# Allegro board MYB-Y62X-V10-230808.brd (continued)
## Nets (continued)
SOC_MCU_RESETZ: C240.1 D44.1 R414.2 U43.L21
SOC_MCU_SPI0_CLK: R158.2 U18.8(B1) U43.L53
SOC_MCU_SPI0_CS0: R159.2 U18.1(B2) U43.L2
SOC_MCU_SPI0_D0: R148.2 R160.2 U43.L3
SOC_MCU_SPI0_D1: R127.2 U43.L4
SOC_MCU_UART0_RXD: R12.1 U43.L1
SOC_MCU_UART0_TXD: R562.1 U43.L58
SOC_MMC1_CLK: D5.2 J2.5(CLK) R37.2 U43.149
SOC_MMC1_CMD: D4.2 J2.3(CMD) R36.2 U43.156
SOC_MMC1_DAT0: D6.2 J2.7(DAT0) R38.2 U43.155
SOC_MMC1_DAT1: D7.2 J2.8(DAT1) R39.2 U43.154
SOC_MMC1_DAT2: D2.2 J2.1(DAT2) R34.2 U43.158
SOC_MMC1_DAT3: D3.2 J2.2(DAT3) R35.2 U43.157
SOC_MMC1_SDCD: D8.2 J2.9(CD) R40.2 U43.159
SOC_MMC2_CLK: R85.1 U43.144
SOC_MMC2_CMD: R84.1 U43.147
SOC_MMC2_DAT0: R78.1 U43.146
SOC_MMC2_DAT1: R80.1 U43.145
SOC_MMC2_DAT2: R82.1 U43.153
SOC_MMC2_DAT3: R83.1 U43.151
SOC_MMC2_SDCD: R308.2 U29.6(INTB/OUT3) U43.148
SOC_OSPI0_CLK: R51.2 U43.132
SOC_OSPI0_CSN0: R54.2 U43.128
SOC_OSPI0_CSN1: R285.1 U43.129
SOC_OSPI0_DQ0: R52.2 U43.139
SOC_OSPI0_DQ1: R53.2 U43.138
SOC_OSPI0_DQ2: R55.2 U43.137
SOC_OSPI0_DQ3: R56.2 U43.140
SOC_OSPI0_DQ4: R58.2 U43.141
SOC_OSPI0_DQ5: R59.2 U43.133
SOC_OSPI0_DQ6: R60.2 U43.136
SOC_OSPI0_DQ7: R61.2 U43.142
SOC_OSPI0_DQS: R62.2 R63.1 U43.135
SOC_OSPI0_ECC_FAIL: R57.2 U43.131
SOC_OSPI0_LBCLK: R63.2 U43.127
SOC_OSPI0_RESETOUT1: U8.1(B) U43.130
SOC_PORZ_OUT: U35.2(A) U39.2(A) U43.L19
SOC_RESET_REQZ: C242.1 D46.1 R416.2 U43.L17
SOC_RESETSTATZ: U8.2(A) U43.L18
SOC_RGMII1_RD0: R358.2 U43.72
SOC_RGMII1_RD0_R: R358.1 R371.2 R372.1 U33.26(RXD0/RXDLY)
SOC_RGMII1_RD1: R356.2 U43.73
SOC_RGMII1_RD1_R: R356.1 R376.1 U33.25(RXD1/CFG_MODE0)
SOC_RGMII1_RD2: R357.2 U43.67
SOC_RGMII1_RD2_R: R357.1 R377.1 U33.24(RXD2/CFG_MODE1)
SOC_RGMII1_RD3: R359.2 U43.71
SOC_RGMII1_RD3_R: R359.1 R378.1 U33.23(RXD3/CFG_MODE2)
SOC_RGMII1_RX_CTL: R355.2 U43.68
SOC_RGMII1_RXC: R354.2 U43.70
SOC_RGMII1_RXC_R: R354.1 R369.2 R374.1 U33.28(RX_CLK/PHYAD1)
SOC_RGMII1_RXCTL_R: R355.1 R368.2 R375.1 U33.27(RX_DV/PHYAD2)
SOC_RGMII1_TD0: R352.2 U43.65
SOC_RGMII1_TD0_R: R352.1 U33.19(TXD0)
SOC_RGMII1_TD1: R350.2 U43.66
SOC_RGMII1_TD1_R: R350.1 U33.18(TXD1)
SOC_RGMII1_TD2: R351.2 U43.61
SOC_RGMII1_TD2_R: R351.1 U33.17(TXD2)
SOC_RGMII1_TD3: R353.2 U43.62
SOC_RGMII1_TD3_R: R353.1 U33.16(TXD3)
SOC_RGMII1_TX_CTL: R349.2 U43.64
SOC_RGMII1_TXC: R348.2 U43.63
SOC_RGMII1_TXC_R: R348.1 U33.21(TX_CLK)
SOC_RGMII1_TXCTL_R: R349.1 U33.20(TX_CTL)
SOC_RGMII2_RD0: R391.2 U43.82
SOC_RGMII2_RD0_R: R391.1 R406.2 R407.1 U37.26(RXD0/RXDLY)
SOC_RGMII2_RD1: R392.2 U43.86
SOC_RGMII2_RD1_R: R392.1 R411.1 U37.25(RXD1/CFG_MODE0)
SOC_RGMII2_RD2: R393.2 U43.85
SOC_RGMII2_RD2_R: R393.1 R412.1 U37.24(RXD2/CFG_MODE1)
SOC_RGMII2_RD3: R394.2 U43.84
SOC_RGMII2_RD3_R: R394.1 R413.1 U37.23(RXD3/CFG_MODE2)
SOC_RGMII2_RX_CTL: R390.2 U43.83
SOC_RGMII2_RXC: R389.2 U43.81
SOC_RGMII2_RXC_R: R389.1 R404.2 R409.1 U37.28(RX_CLK/PHYAD1)
SOC_RGMII2_RXCTL_R: R390.1 R403.2 R410.1 U37.27(RX_DV/PHYAD2)
SOC_RGMII2_TD0: R383.2 U43.75
SOC_RGMII2_TD0_R: R383.1 U37.19(TXD0)
SOC_RGMII2_TD1: R388.2 U43.76
SOC_RGMII2_TD1_R: R388.1 U37.18(TXD1)
SOC_RGMII2_TD2: R384.2 U43.80
SOC_RGMII2_TD2_R: R384.1 U37.17(TXD2)
SOC_RGMII2_TD3: R385.2 U43.74
SOC_RGMII2_TD3_R: R385.1 U37.16(TXD3)
SOC_RGMII2_TX_CTL: R387.2 U43.77
SOC_RGMII2_TXC: R386.2 U43.79
SOC_RGMII2_TXC_R: R386.1 U37.21(TX_CLK)
SOC_RGMII2_TXCTL_R: R387.1 U37.20(TX_CTL)
SOC_RGMII_MDC: R381.2 R542.1 U37.14(MDC) U43.L23
SOC_RGMII_MDIO: R382.2 R543.1 U37.15(MDIO) U43.L24
SOC_SPI0_CLK: J7.3 U43.L51
SOC_SPI0_CS0: R136.2 R138.1 U43.L50
SOC_SPI0_CS1: R135.2 R137.1 U43.L44
SOC_SPI0_D0: R133.2 R139.1 U43.L52
SOC_SPI0_D1: R134.2 R140.1 U43.L45
SOC_UART0_CTSN: R554.1 U43.124
SOC_UART0_RTSN: R492.1 R493.1 R494.1 U43.123
SOC_UART0_RXD: R560.1 U43.125
SOC_UART0_TXD: R5.1 U43.126
SOC_UART1_CTSN: U43.L12 U47.42(UART_RTS)
SOC_UART1_DCDN: R142.1 U43.L5
SOC_UART1_DSRN: R291.1 R444.1 R489.1 U43.L6
SOC_UART1_DTRN: R260.1 U43.L10
SOC_UART1_RIN: R263.1 U43.L9
SOC_UART1_RTSN: U43.L11 U47.43(UART_CTS)
SOC_UART1_RXD: R81.1 U43.L7
SOC_UART1_TXD: R79.1 U43.L8
SOC_UART4_RXD: R283.1 U43.L25
SOC_UART4_TXD: R280.1 U43.L26
SOC_USB0_DM: L9.1 U43.41
SOC_USB0_DP: L9.4 U43.40
SOC_USB0_DRVVBUS: R317.2 U43.L46
SOC_USB1_DM: U28.30(DMU) U43.44
SOC_USB1_DP: U28.31(DPU) U43.43
SOC_USB1_DRVVBUS: R274.1 U43.L49
SOC_VOUT0_DATA0: R163.1 U43.95
SOC_VOUT0_DATA1: R164.1 U43.107
SOC_VOUT0_DATA2: R165.1 U43.101
SOC_VOUT0_DATA3: R166.1 U43.106
SOC_VOUT0_DATA4: R167.1 U43.99
SOC_VOUT0_DATA5: R168.1 U43.105
SOC_VOUT0_DATA6: R169.1 U43.92
SOC_VOUT0_DATA7: R170.1 U43.98
SOC_VOUT0_DATA8: R171.1 U43.93
SOC_VOUT0_DATA9: R172.1 U43.L29
SOC_VOUT0_DATA10: R173.1 U43.117
SOC_VOUT0_DATA11: R174.1 U43.L27
SOC_VOUT0_DATA12: R175.1 U43.97
SOC_VOUT0_DATA13: R176.1 U43.L30
SOC_VOUT0_DATA14: R177.1 U43.94
SOC_VOUT0_DATA15: R178.1 U43.L28
SOC_VOUT0_DATA16/BOOTMODE08: R179.1 R197.1 U43.115
SOC_VOUT0_DATA17/BOOTMODE09: R180.1 R199.1 U43.113
SOC_VOUT0_DATA18/BOOTMODE10: R181.1 R200.1 U43.112
SOC_VOUT0_DATA19/BOOTMODE11: R182.1 R201.1 U43.116
SOC_VOUT0_DATA20/BOOTMODE12: R183.1 R202.1 U43.96
SOC_VOUT0_DATA21/BOOTMODE13: R184.1 R203.1 U43.103
SOC_VOUT0_DATA22/BOOTMODE14: R185.1 R204.1 U43.108
SOC_VOUT0_DATA23/BOOTMODE15: R186.1 R205.1 U43.102
SOC_VOUT0_DE: R194.1 U43.87
SOC_VOUT0_HSYNC: R196.1 U43.88
SOC_VOUT0_PCLK: R198.1 U43.89
SOC_VOUT0_VSYNC: R195.1 U43.90
SOC_WKUP_UART0_RXD: U43.L20 U46.8(B1)
SOC_WKUP_UART0_TXD: U43.L31 U46.1(B2)
USB0CC1: C158.1 R314.1 U29.1(CC1)
USB0CC2: C160.1 R315.1 U29.2(CC2)
USB_5G_DM: J19.9(IO_9) U28.17(DM3)
USB_5G_DP: J19.7(IO_7) U28.18(DP3)
USB_HUB_RST: R487.1 U42.6(P02)
USB_I2C_SCL: R454.2 R473.2 U29.8(SCL/OUT2)
USB_I2C_SDA: R474.2 R494.2 U29.7(SDA/OUT1)
USB_UART_DM: L6.1 U19.4(UDM)
USB_UART_DP: L6.4 U19.3(UDP)
USBA0_DM: D27.2 J16.A2(USBHMA) U28.20(DM2)
USBA0_DP: D28.2 J16.A3(USBHPA) U28.21(DP2)
USBA1_DM: D30.2 J16.B2(USBHMB) U28.23(DM1)
USBA1_DP: D29.2 J16.B3(USBHPB) U28.24(DP1)
USBC_ID: R309.2 R319.1 U29.9(ID)
USER_LED: D54.2(K) U42.8(P04)
USIM1_CLK: J19.32(IO_32) R327.2
USIM1_DATA: J19.34(IO_34) R325.2
USIM1_DET: J17.4(CD) J19.66(IO_66)
USIM1_RST: J19.30(IO_30) R326.2
USIM2_CLK: J19.44(IO_44) R333.2
USIM2_DATA: J19.42(IO_42) R335.2
USIM2_DET: J18.4(CD) J19.40(IO_40)
USIM2_RST: J19.46(IO_46) R332.2
VIO: C96.1 C98.1 U19.5(VIO) U19.6(V3)
W_DISABLE1_N: J19.8(IO_8) R336.2
WAKE_ON_WAN_N: J19.23(IO_23) TP20.1(PIN1)
WIFI_2V2: C273.1 C274.1 C275.1 L13.1 U47.26(2.2VIN)
WWAN_LED_N: D55.2(K) J19.10(IO_10)
N19629412: C321.1 U27.14(LINEIN_L)
N19629418: C322.1 U27.13(LINEIN_R)
N19629536: J14.3(AUD_GND) R570.1
N19629600: C131.1 U27.10(VAG)
N19629602: C132.1 U27.18(CPFLT)
N19629628: R299.1 U27.31(CTRL_ADR0_CS)
N20386876: J9.9 R152.1
N20386882: J9.6 R150.1
N20386885: J9.7 R151.1
N20386918: J9.2 R148.1
N20390587: Q4.1(G) R127.1 R132.1
N20390701: Q4.3(D) R108.2 R112.2
N20390757: C77.1 C78.1 Q3.2(S) R107.2 R108.1 R117.2
N20390883: C78.2 Q3.1(G) R112.1
N20656670: R288.1 Y2.3(OUT/OUTPUT)
N21392930: L11.1 U33.32(LX)
N21392969: R346.2 R542.2 U33.14(MDC)
N21392972: R347.2 R543.2 U33.15(MDIO)
N21393016: R360.2 U33.34(INT_N/PME_N)
N21393026: R362.1 U33.48(RBIAS)
N21393171: C202.1 C203.1 J22.5(CT1) J22.6(CT2)
N21405925: L12.1 U37.32(LX)
N21406011: R395.2 U37.34(INT_N/PME_N)
N21406021: R397.1 U37.48(RBIAS)
N21406166: C221.1 C222.1 J23.5(CT1) J23.6(CT2)
N21450803: R231.2 SW3.2(ON2)
N21450805: R227.2 SW3.3(ON3)
N21473108: C147.1 U28.11(XOUT) Y3.1
N21476694: C146.1 U28.12(XIN) Y3.3
N21477956: R306.2 R487.2 U28.34(XRSTJ)
N21522281: C182.1 D32.2 J17.2(RST) R326.1
N21522507: C184.1 D34.2 J17.7(I/O) R322.2 R325.1
N21526256: C183.1 D33.2 J17.3(CLK) R327.1 TP16.1(PIN1)
N21526274: C199.1 D38.2 J18.7(I/O) R331.2 R335.1
N21544762: C175.1 C176.1 D31.2 J17.1(VCC) R323.2
N21577420: C171.1 U31.1(BS)
N21577422: C171.2 L10.1 U31.6(LX)
N21577513: R324.2 R329.1 U31.4(EN)
N21577585: C177.2 R328.2 R330.1 U31.3(FB)
N21670486: C239.1 D44.2 D45.2 S1.3 S1.4
N21676766: C241.1 D46.2 D47.2 S2.3 S2.4
N21683802: R266.2 R269.2 U23.3((R)RXD)
N21683845: R267.2 R270.1 U23.12(A)
N21683857: R268.2 U23.6((D)TXD)
N21683901: R272.1 R275.1 U23.13(B)
N21683929: R274.2 R276.1 U23.4(R\E\\) U23.5(DE)
N21684314: R278.2 R283.2 U25.3((R)RXD)
N21684387: R280.2 U25.6((D)TXD)
N21684482: R285.2 R287.1 U25.4(R\E\\) U25.5(DE)
N21714485: R279.2 R281.1 U25.12(A)
N21714524: R284.1 R286.1 U25.13(B)
N21838021: C81.1 C82.1 FB3.1 J7.5 J7.6
N21848668: C138.1 U28.38(VD5_IN)
N21848671: R302.1 U28.40(TEST)
N21849105: R300.2 U28.48(OVCB1)
N21849965: R301.2 U28.39(VD33_OUT)
N21884472: D1.2 F1.2 L1.1
N21885565: R3.2 U1.7(PG)
N21885584: C11.1 U1.1(BS)
N21885634: R4.2 R6.1 U1.9(EN)
N21885693: TP3.1(TP) U1.8(MODE)
N21885737: C19.1 R7.2
N21885739: C19.2 R8.2 R9.1 U1.11(FB)
N21885780: TP5.1(TP) U1.10(ILMT)
N21885830: C20.1 U1.12(BYP)
N21893632: C9.1 U1.13(VCC)
N21900346: C37.2 R18.2 R20.1 U3.7(FB)
N22230603: C126.1 R289.2 Y2.1(EN/VCONT/NC)
N22232243: C86.1 R149.2 Y1.1(EN/VCONT/NC)
N22247036: R248.2 U19.9(RST)
N22324946: D23.2 J15.A6(DP1) J15.B6(DP2) L9.3
N22324958: D24.2 J15.A7(DN1) J15.B7(DN2) L9.2
N22324997: R310.2 U29.5(ADR/CON_DET)
N22325047: R311.2 U29.11(EXT_SEL(ENB))
N22325067: R312.2 R313.1 U29.3(PORT)
N22325125: D25.2 J15.A5(CC1) R314.2
N22325136: D26.2 J15.B5(CC2) R315.2
N22325338: Q5.3(D) R316.2 R317.1 U30.4(EN)
N22325344: R318.2 U30.3(F\L\A\G\)
N22325474: Q5.1(G) R319.2
N22325526: C166.1 C167.1 F2.1 J16.A1(VCC#A1)
N22325538: C168.1 C169.1 F3.1 J16.B1(VCC#B1) TP14.1(TP)
N22348627: J6.27(BL_CTR) R137.2
N22348634: J6.28(TP_CS) R139.2
N22348696: J6.36(TP_PEN) R144.2
N22355541: J5.27(BL_CTR) R138.2
N22355547: J5.28(TP_CS) R140.2
N22355619: J5.36(TP_PEN) R146.2
N22387016: C21.1 U2.13(VCC)
N22387130: R10.2 U2.7(PG)
N22387188: C25.1 U2.1(BS)
N22387215: R11.2 R15.1 U2.9(EN)
N22387217: TP6.1(TP) U2.8(MODE)
N22387362: TP8.1(TP) U2.10(ILMT)
N22387364: C31.2 R14.2 R16.1 U2.11(FB)
N22387368: C31.1 R13.2
N22387403: C32.1 U2.12(BYP)
N22404559: C197.1 D36.2 J18.2(RST) R332.1
N22407290: C198.1 D37.2 J18.3(CLK) R333.1
N22407725: D55.1(A) R427.2
N22483474: R104.1 U12.4(Y)
N22483498: C72.1 R106.2
N22483568: R105.1 U13.4(Y)
N22513317: R218.2 SW2.2(ON2)
N22513319: R219.2 SW2.3(ON3)
N22513321: R220.2 SW2.4(ON4)
N22513323: R230.2 SW3.1(ON1)
N22515068: R229.2 SW2.1(ON1)
N22517589: J22.11(YELLOW+) R344.2
N22517591: J22.13(GREEN+) R345.2
N22525013: J23.13(GREEN+) R380.2
N22525015: J23.11(YELLOW+) R379.2
N22597309: R192.2 R461.1 R491.1
N22610391: R539.2 U40.10(NINT)
N22680350: J26.1 U46.5(A1)
N22680357: J26.2 U46.4(A2)
N22683837: C263.1 R502.2 U47.2(RF0)
N22683839: C264.1 D56.2 J27.2(IN) R502.1
N22683943: R81.2 U47.40(UART_TX)
N22683961: R79.2 U47.41(UART_RX)
N22683997: C265.1 R504.2 U47.9(RF1)
N22684003: C266.1 D57.2 J28.2(IN) R504.1
N22684239: R511.2 Y6.1(EN/VCONT/NC)
N22684315: R512.1 Y6.3(OUT/OUTPUT)
N22684386: L13.2 U47.25(LX_OUT)
N22685134: R69.2 R85.2 U47.18(SD_CLK)
N22685150: R70.2 R84.2 U47.17(SD_CMD)
N22685166: R71.2 R83.2 U47.19(SD_D3)
N22685182: R72.2 R82.2 U47.20(SD_D2)
N22685198: R74.2 R80.2 U47.22(SD_D1)
N22685204: R76.2 R78.2 U47.21(SD_D0)
N22709458: R514.2 U48.72(CI2CA)
N22710105: R515.1 U48.36(SPDIF)
N22710530: R516.2 U48.41(SD0)
N22712478: R517.1 U48.69(IO_SEL)
N22712757: R518.1 U48.56(EXT_SWING)
N22714174: R521.2 R545.1 U50.3(EN)
N22724008: Q2.1(B) R524.2
N22724271: R532.2 U53.5(A1)
N22724282: R533.2 U53.4(A2)
N22746676: C294.1 R535.2 Y7.1(EN/VCONT/NC)
N22751077: D58.2 J29.18(+5V)
N22751165: D59.2 R522.1 R523.1
N22767924: R252.2 U20.3(TXD)
N22767926: L7.1 U20.7(CANH)
N22767928: L7.4 R253.1 R255.1
N22767957: L7.3 R254.1 R256.1
N22767970: R257.2 U20.2(RXD)
N22767972: L7.2 U20.6(CANL)
N22768026: C104.1 R255.2 R256.2
N22768266: R260.2 U22.3(TXD)
N22768268: L8.1 U22.7(CANH)
N22768270: L8.4 R261.1 R264.1
N22768305: L8.3 R262.1 R265.1
N22768318: R263.2 U22.2(RXD)
N22768320: L8.2 U22.6(CANL)
N22768352: C112.1 R264.2 R265.2
N22843605: C318.1 U50.4(BP/FB)
N22857632: R161.2 U48.45(SCK)
N22857662: R162.2 U48.44(WS)
N22863110: R142.2 R290.1 R445.1 R452.1
N22863348: R451.1 R453.1 R454.1 R554.2
N22865159: R555.1 U54.15(NOE)
N22941387: Q1.3(D) R5.2 R558.2
N22941439: Q6.2(S) R559.2 R560.2
N22941491: Q7.3(D) R561.2 R562.2
N22941543: Q8.2(S) R12.2 R563.2
N22973519: R419.1 U40.7(FOE)
N22982457: JP1.2(E2) R567.1
N22991878: C321.2 C322.2 R569.1
N23013826: JP2.1(E1) R571.2
N23013829: JP3.1(E1) R572.2
N23945057: D50.1(A) R423.2
N24701406: R307.1 U28.28(REXT)
N24701492: R305.2 U28.35(VBUSM)
N24701498: R304.2 U28.36(BUS_B)
N24701504: R303.1 U28.37(DIS_REG)
N24926165: C195.1 C196.1 D35.2 J18.1(VCC) R334.2
N25388780: D39.2 J20.1(CENTER1) J21.2(IN)
N25609213: D53.1(A) R424.2
N25609260: D54.1(A) R426.2

Pads without a net: J1 3; J4 6 17 18 19; J5 1 4 5 6 23 24 26 29 31 32 35 37 38 39 40; J6 1 4 5 6 23 24 26 29 31 32 35 37 38 39 40; J9 3; J11 25 26 27 28 29 30; J12 A2 A3 A8 A10 A11 B2 B3 B8 B10 B11; J14 5 6 7 8; J15 A2 A3 A8 A10 A11 B2 B3 B8 B10 B11; J17 6; J18 6; J19 20 22 24 26 28 29 31 35 37 41 43 47 49 50 52 53 54 55 56 58 60 62 64; J21 1; J27 1; J28 1; J29 13 14; NOREF#3 1; NOREF#9 1; NOREF#12 1; NOREF#13 1; NOREF#14 1; NOREF#16 1; NOREF#17 1; NOREF#20 1; NOREF#21 1; NOREF#22 1; NOREF#23 1; NOREF#25 1; NOREF#26 1; NOREF#29 1; SW1 1; SW3 4 5; TEMPLATE1 1; U4 1; U19 1 10 11 14 15 16 17 18 19 22 23 24; U23 11 14; U25 11 14; U27 8 9 11 12 17 19 22 28; U28 2 4 14 15 42 43 44 45 46 47; U32 5; U33 33 40 41 42 43 44; U34 5; U36 5; U37 33 40 41 42 43 44; U38 5; U40 1 3 5 12; U42 11 13 14 15 16 17 18 19 20; U47 12 13 14 16 24 27 28 29 30 33 35 37 38 44 45 46 47 48 50; U48 37 39 40 50 71; U54 14; U55 A2 A3 B1 B5 C5

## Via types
v1: diameter 0.508, hole 0.254, TOP to BOTTOM, 1788 vias
v2: diameter 0.406, hole 0.203, TOP to BOTTOM, 761 vias

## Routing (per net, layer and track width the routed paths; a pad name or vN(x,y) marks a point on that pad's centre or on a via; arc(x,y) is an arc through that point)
AVCC_1V2: length 2.7
  TOP w0.254: U48.60 v2(154.61,28.86) ; U48.66 v2(154.61,31.86)
  BOTTOM w0.254: C291.1 153.93,28.86 v2(154.61,28.86) ; C292.1 154.59,31.88 v2(154.61,31.86)
  vias: v2(152.45,22.99) v2(152.95,22.99)
DVDD_RGMII1: length 30.2
  TOP w0.203: v1(90.42,36.58) 90.47,36.52 U33.29
  TOP w0.381: v1(96.9,30.91) 96.9,30.45 96.52,30.07 R347.1 R346.1
  ART03 w0.305: v1(93.31,40.89) 92.96,40.89 92.39,40.33 91.85,40.33 91.28,40.89 v1(90.25,40.89)
  BOTTOM w0.381: R368.1 R369.1 v1(90.25,40.89) ; v1(93.31,40.89) 93.31,39.76 92.92,39.37 R371.1 ; C209.1 C210.1
  BOTTOM w0.508: C210.1 94.81,35.49 95.96,34.34 95.96,31.7 96.74,30.91 v1(96.9,30.91) ; v1(90.25,40.89) 90.25,41.1 89.75,41.61 88.9,41.61 88.46,41.17 88.46,37.69 89.1,37.06 89.93,37.06 v1(90.42,36.58) 91.02,35.98 C209.1
DVDD_RGMII2: length 29.9
  TOP w0.203: v1(113.71,36.58) 113.77,36.52 U37.29
  TOP w0.381: R381.1 R382.1 v2(120.15,30.07)
  BOTTOM w0.381: R406.1 115.96,39.79 115.14,40.61 114.6,40.61 114.49,40.5 114.49,40.5 114.16,40.17 114.16,39.33 R403.1 R404.1 113.29,40.26 112.91,40.64 111.6,40.64 109.5,38.53 109.5,36.88 109.8,36.58 112.24,36.58 112.42,36.75 113.53,36.75 v1(113.71,36.58) 114.31,35.98 C228.1 C229.1 116.65,35.49 118.74,33.4 118.74,31.48 v2(120.15,30.07)
GND: length 701.6
  TOP w0.203: U37.38 109.11,34.16 v1(108.98,34.29) ; 79.4,94.74 78.53,94.74 v2(78.06,94.27) ; v1(85.77,33.91) 86.02,34.16 U33.38 ; U53.2 148.51,49.78 v1(148.64,49.66) ; U29.10 v1(56.69,19) ; U37.39 109.2,33.76 v1(108.98,33.53) ; U18.2 v1(155.74,69.72) ; v1(19.73,69.09) U15.B2 U15.B1 v1(19.73,66.75) ; U33.39 86.38,33.76 v1(85.9,33.27) ; v1(19.73,75.56) U17.B3 U17.B2 U17.B1 v1(19.73,72.14) ; v1(11.73,110.11) 11.99,109.85 U46.2 ; v1(155.75,73.97) 155.56,73.78 U45.2 ; v1(19.73,60.2) U16.B1 U16.B2 U16.B3 v1(19.73,63.12)
  TOP w0.254: J29.8 v1(154.2,8.89) ; v1(129.97,26.8) 129.61,26.44 U28.16 ; J29.11 v1(152.7,8.89) ; J15.A12 v1(58.76,8.6) ; v1(58.34,4.32) 58.5,4.48 J15.B1 ; J12.B12 68.1,5.48 68.16,5.42 68.16,4.66 v1(68.37,4.45) ; v1(53.64,4.45) 53.06,5.03 53.06,5.42 53,5.48 J15.B12 ; U48.57 v1(154.61,27.36) ; v1(155.8,14.22) U51.B2 U51.B1 v1(157.93,14.22) ; U42.3 v1(140.8,69.59) ; U28.8 v1(127.8,28.84) ; J12.B1 73.6,4.59 v1(73.33,4.32) ; v1(132.98,26.63) 132.61,26.26 U28.22 ; v1(70.18,16.79) 70.36,16.97 U19.2 ; U42.21 v1(146.07,68.94) ; v1(42.59,25.27) 43,24.86 U27.32 ; U28.6 v1(125.27,29.84) ; U48.55 v1(154.61,26.36) ; v1(125.52,32.51) 125.69,32.34 U28.1 ; v1(41.45,24.13) 41.45,24 41.73,23.72 U27.1 ; U42.12 137.25,63.73 v1(136.52,64.47) ; v1(125.27,30.61) 125.53,30.34 U28.5 ; U28.7 v1(128.44,29.34) ; U48.70 v1(154.68,33.86) ; v1(152.55,14.22) U52.B2 U52.B1 v1(154.68,14.22) ; v1(133.78,26.92) 133.86,26.84 U28.25 ; U28.33 v1(133.65,30.84) ; J29.5 v1(155.7,8.89) ; v1(125.4,27.81) 125.42,27.84 U28.10 ; v1(19.73,57) U14.B2 U14.B1 19.73,53.52 v1(18.97,52.76) ; v1(44.78,21.95) U27.33 44,22.72 U27.3 ; v1(67.99,8.38) 68.36,8.02 J12.A1 ; J29.17 v1(149.7,8.89) ; J29.2 v1(157.2,8.89) ; v2(78.06,94.27) 78.06,93.1 78.78,92.39 v1(78.78,92.28) 79.26,92.76 80.77,92.76 v2(81.25,92.28) ; J12.A12 v1(73.86,8.49) ; U42.2 v1(140.28,70.24) ; J15.A1 v1(53.26,8.51) ; 79.78,94.03 80.18,93.62 81.35,93.62 v2(82.04,92.94) ; U48.63 v1(154.76,30.36) ; v1(73.94,34.91) U54.8 ; U48.43 v1(147.89,24.78)
  TOP w0.305: U13.3 v1(154.49,80.63) ; U55.E5 v2(97.98,98.24) ; v1(11.86,59.56) 10.85,60.57 J8.14 ; v1(16.56,72.36) 16.33,72.59 J8.25 ; U55.C1 v2(93.01,100.66) ; U55.B3 v2(95.98,102.09) ; J8.13 v1(17.29,60.57) ; J8.26 v1(11.38,72.59)
  TOP w0.381: v1(105.56,33.26) 105.55,33.27 103.01,33.27 102.66,32.93 v1(102.66,29.94) ; v1(105.56,33.26) Y5.4 ; v1(105.56,33.26) 106.6,33.26 C220.2 107.68,32.54 108.34,31.88 v1(108.98,31.88) ; D41.1 v1(96.22,25.15) ; U50.2 v1(146.86,53.72) ; v1(108.47,21.97) U36.2 108.47,24.26 v1(108.21,24.51) ; C241.2 161.21,26.16 v1(160.83,25.78) ; C137.2 v1(43.99,28.96) ; D27.1 v1(132.63,21.59) ; U43.24 v1(63.62,66.33) ; v1(50.76,95.21) 50.76,92.8 51.1,92.46 56.31,92.46 57.2,93.34 57.2,95.25 56.82,95.63 v1(56.49,95.63) ; v1(50.76,95.21) Y6.2 ; v1(50.76,95.21) 50.76,96.56 51.48,97.28 52.75,97.28 v1(53.89,98.42) ; v1(62.86,103.2) 62.62,102.96 U47.39 ; C253.2 v1(148.57,71.7) ; R287.2 v1(119.49,90.87) ; U39.3 v1(65.74,37.12) ; v1(52.38,25.02) 49.32,25.02 48.56,24.26 v1(48.56,22.73) ; v1(52.38,25.02) 53.01,25.02 53.51,24.51 53.51,21.11 v1(52.8,20.4) 52.75,20.35 52.75,18.67 52.12,18.03 v1(51.23,18.03) 50.92,18.35 C126.2 50.21,18.8 49.83,19.18 49.83,20.7 v1(49.45,21.08) ; v1(52.38,25.02) Y2.2 ; v1(85.81,21.97) U32.2 85.81,24.26 v1(85.56,24.51) ; J2.10 87.07,113 87.04,113.03 ; J2.10 88.4,111.85 ; J2.10 87.07,110.77 ; R234.2 v1(158.8,52.96) ; U43.9 v1(63.62,81.33) ; R567.2 v1(79.48,36.42) ; v1(125.4,27.81) 124.89,28.32 124.89,28.57 124.45,29.01 C147.2 123.55,29.72 122.88,29.72 v1(122.87,29.73) ; v1(104.34,28.09) 105.13,28.09 R397.2 ; v1(161.08,17.78) 161.41,18.1 C239.2 D45.1 ; S2.2 S2.1 v1(163.02,23.15) ; U47.4 56.84,115.8 ; v1(154.2,49.91) 154.2,49.91 C281.2 ; v1(145.72,24.89) 145.72,19.82 145.33,19.44 v1(144.71,19.44) ; D50.2 v1(92.25,116.08) ; U43.12 v1(63.62,78.33) ; v1(85.68,31.88) 84.92,31.88 84.26,32.54 C201.2 83.31,33.26 v1(82.26,33.26) ; C57.2 v1(90.41,110.31) ; D5.1 82.22,106.53 v1(82.11,106.43) ; D23.1 v1(55.31,11.81) ; D6.1 v1(83.36,106.43) ; U43.100 v1(108.94,65.33) ; U43.91 v1(108.96,56.33) ; v1(85.17,30.35) 84.71,29.88 C205.2 84.03,29.81 83.16,28.93 79.75,28.93 79.37,29.31 v1(79.37,29.94) ; Y3.2 v1(121.07,25.41) ; v1(121.07,25.41) 120.57,25.41 120.19,25.79 120.19,29.34 120.59,29.73 122.86,29.73 v1(122.87,29.73) ; v1(121.07,25.41) 123.88,25.41 124.25,25.78 C146.2 125.79,26.36 v2(126.28,25.86) ; Y3.4 v1(122.87,29.73) ; D43.1 v1(118.12,25.48) ; D24.1 v1(56.71,11.81) ; R362.2 v1(81.23,28.19) ; R517.2 v2(157.84,34.42) ; U47.32 55.94,98.63 v1(55.7,98.4) C272.2 R513.2 55.6,95.63 v1(56.49,95.63) ; v1(115.45,21.97) U38.2 115.45,24.26 v1(115.2,24.51) ; v1(144.71,19.44) 139.99,19.44 139.04,20.39 v1(139.04,21.65) C294.2 139.87,22.23 140.64,22.99 142.92,22.99 143.3,23.37 143.3,24 v1(144.32,25.02) ; v1(144.71,19.44) Y7.2 ; U43.48 v1(71.78,44.35) ; U43.109 v1(108.94,74.33) ; C203.2 v1(88.73,25.27) ; C70.2 v1(160,86.61) ; U43.30 v1(63.62,60.33) ; C170.1 v1(145.66,16.18) ; C170.1 144.45,16.16 v1(144.45,15.24) ; C170.1 v1(143.1,16.18) ; v1(102.66,29.94) 102.66,29.31 103.04,28.93 106.92,28.93 107.32,29.34 C224.2 108,29.88 v1(108.47,30.35) ; v1(102.66,29.94) Y5.2 ; C88.2 v1(160.96,69.6) ; R419.2 v1(115.18,64.49) ; C87.2 v1(151.18,69.6) ; R245.2 R246.2 ; R246.2 R247.2 ; R246.2 v1(130.86,55.75) ; U47.7 54.14,115.81 ; D47.1 v1(161.21,28.07) ; v1(82.39,112.81) 82.32,112.73 J2.6 82.32,109.75 v1(82.72,109.35) ; U35.3 v1(71.75,37.15) ; D3.1 v1(78.02,106.43) ; U43.27 v1(63.62,63.33) ; R515.2 140.55,23.72 v1(139.72,23.72) ; D2.1 v1(76.88,106.43) ; C138.2 v1(132.89,37.59) ; R307.2 138.41,28.7 v2(138.98,28.7) ; v1(163.02,30.39) S3.1 S3.2 ; v1(50.81,17.31) FB6.1 v1(50.08,18.03) ; v1(101.65,17.86) 101.65,17.41 R574.2 100.63,17.41 v1(100.63,17.86) ; U47.8 53.24,115.8 ; U43.69 v1(92.78,45.17) ; D29.1 v1(136.6,21.59) ; U43.119 v1(108.76,84.33) ; v1(120.44,55.83) R241.2 R242.2 R243.2 R244.2 ; U43.57 v1(80.78,44.21) ; R232.2 R233.2 158.16,49.28 157.83,49.61 v1(157.83,49.99) ; U47.3 57.74,115.79 ; C221.2 v1(112.28,25.53) ; C72.2 v1(154.1,83.95) 154.59,84.44 U12.3 ; C248.2 C247.2 D49.1 v1(161.28,35.12) ; C271.2 56.43,95.1 56.49,95.15 v1(56.49,95.63) ; U47.6 55.04,115.82 ; U43.15 v1(63.62,75.33) ; U43.33 v1(63.62,57.33) ; Q5.2 v1(56.23,29.34) ; U43.152 v1(78.78,92.28) ; U43.51 v1(74.78,45.17) ; D28.1 v1(134.03,21.59) ; U47.10 51.44,115.74 ; v1(77.78,44.96) U43.54 ; U43.36 v1(63.62,54.33) ; C153.2 v1(54.4,17.65) ; v1(163.08,15.27) S1.1 S1.2 ; D40.1 v1(82.63,25.27) ; v1(82.26,33.26) 82.25,33.27 79.8,33.27 79.37,32.84 v1(79.37,29.94) ; v1(82.26,33.26) Y4.4 ; C222.2 v1(111.39,25.53) ; v1(93.43,21.97) U34.2 93.43,24.26 v1(93.18,24.51) ; v1(79.37,29.94) Y4.2 ; R249.2 v1(68.69,14.04) ; D42.1 105.29,25.31 v1(105.15,25.45) ; C158.2 v1(53.64,16.1) ; R276.2 v1(132.19,90.93) ; R313.2 v1(62.02,17.02) ; R132.2 v1(15.29,94.23) ; C202.2 v1(89.62,25.27) ; D13.1 v1(73.52,11.88) ; U43.134 96.78,91.73 v1(96.31,92.2) ; Q4.2 19.68,91.39 v1(19.91,91.16) ; U43.21 v1(63.62,69.33) ; R9.2 v1(44.62,80.52) ; C77.2 v1(19.73,84.58) ; C154.2 v1(62.02,18.8) ; U47.23 v1(47.09,102.96) ; U43.60 v1(83.78,44.24) ; v1(87.85,92.18) 87.78,92.1 U43.143 ; R302.2 v1(131.11,37.59) ; R6.2 44.62,77.34 45,77.72 v1(45,78.11) ; C280.2 144.19,49.91 v1(144.06,50.04) ; U47.5 55.94,115.81 ; D10.1 72.44,9.53 v2(72,9.09) ; D30.1 v1(135.2,21.59) ; D25.1 v1(53.66,11.81) ; U47.11 50.54,115.75 ; D8.1 v1(85.52,106.43) ; C160.2 v1(58.44,16.1) ; D4.1 v1(79.04,106.43) ; U43.18 v1(63.62,72.33) ; D7.1 v1(84.5,106.43) ; C319.2 R555.2 v1(63.04,31.5) ; D12.1 v1(68.69,11.88) ; R525.2 v1(143.46,18.35) ; R527.2 R518.2 v1(151.35,18.35) ; D11.1 69.78,9.53 v2(70.22,9.09) ; U47.1 59.54,115.88 ; D26.1 v1(58.44,11.81) ; U8.3 v1(96.38,113.34) ; U43.78 v1(101.78,44.58) ; C71.2 v1(160.7,81.92) ; U43.39 v1(63.62,51.33) ; R15.2 v1(40.56,31.62)
  TOP w0.457: C263.2 v1(60.35,116.48) ; C264.2 v1(61.57,116.48)
  TOP w0.508: C265.2 v1(50.17,116.48) ; D57.1 v1(46.28,119.5) ; v1(164.49,10.91) 164.49,10.29 R526.1 163.52,10.29 v1(163.52,10.91) ; J27.4 v1(62.08,123.07) ; J28.3 v1(48.46,123.07) ; v1(78.53,102.97) 79.35,102.97 80.06,103.68 C54.2 ; v1(165.81,11.06) 165.81,10.44 C279.2 166.77,10.44 v1(166.77,11.06) ; D56.1 v1(64.26,119.5) ; C266.2 v1(47.38,116.48) ; J28.4 v1(45.86,123.07) ; J27.3 v1(64.68,123.07)
  TOP w0.635: 70.21,121.4 J2.13 ; J2.13 71.32,120.44 ; J2.13 71.32,122.35 ; J2.13 72.42,121.4 ; 85.81,121.4 J2.12 ; J2.12 86.92,122.35 ; J2.12 86.92,120.44 ; J2.12 88.02,121.4 ; 70.91,111.8 J2.11 ; J2.11 71.92,112.75 ; J2.11 72.92,111.8 ; J2.11 71.92,110.84
  BOTTOM w0.203: 82.27,99.09 82.27,102.18 85.52,105.44 v1(85.52,106.43) 85.52,107.01 85.04,107.49 82.95,107.49 82.11,106.65 v1(82.11,106.43) 81.66,105.97 81.66,105.36 81.94,105.08 82.34,105.08 82.88,105.61 82.88,105.82 83.36,106.3 v1(83.36,106.43) v1(84.5,106.43) 84.55,106.38 84.55,105.66 84.27,105.38 84.27,105.37 81.4,102.5 81.4,99.53 80.51,98.65 80.51,96.32 79.83,95.63 v1(79.55,95.63) 79.55,95.07 79.22,94.74 78.53,94.74 v2(78.06,94.27) 78.58,93.75 79.57,93.75 81.43,95.61 81.43,98.25 82.27,99.09
  BOTTOM w0.254: R299.2 42.59,24.88 v1(42.59,25.27) ; v1(159.05,45.34) 157.53,46.86 157.02,46.86 156.64,47.24 156.64,49.61 157.02,49.99 v1(157.83,49.99) 161.82,49.99 163.04,48.77 163.75,48.77 v1(163.78,48.79)
  BOTTOM w0.305: J19.3 28,51.4 v1(27.61,51.79) ; v1(28.5,49.12) J19.5 v1(28.5,51.79) ; J5.7 16.15,79.93 v1(16.48,80.26) ; v1(38.5,49.05) J19.45 v1(38.5,51.79) ; J6.13 v1(16.15,48.1) ; J5.13 v1(16.48,76.93) ; v1(35.5,49.05) J19.33 v1(35.5,51.79) ; J5.16 v1(17.06,75.43) ; J19.71 v1(45,49.05) ; J5.10 v1(16.56,78.43) ; v1(40,51.79) J19.51 v1(40,49.05) ; J5.19 v1(17.19,73.93) ; v1(37,49.05) J19.39 v1(37,51.79) ; J5.30 v1(16.48,68.43) ; v1(167.81,47.62) 167.29,48.15 J9.10 ; v1(34,49.05) J19.27 v1(34,51.79) ; J5.22 16.49,72.43 v1(16.56,72.36) ; J9.8 163.02,47.15 v1(162.35,46.48) ; J5.25 v1(16.48,70.93) ; J6.16 v1(16.15,46.6) ; J6.25 v1(16.15,42.1) ; J19.73 v1(45.5,51.79) ; v1(30,49.12) J19.11 v1(30,51.79) ; J6.22 v1(16.15,43.6) ; J6.30 v1(16.15,39.6) ; J6.7 v1(16.15,51.1) ; J6.19 v1(16.15,45.1) ; J6.10 v1(16.15,49.6) ; J19.57 v1(41.5,51.79)
  BOTTOM w0.381: v1(163.02,23.15) 162.73,22.86 C242.2 ; v1(118.03,40.01) 118.03,39.59 R411.2 R407.2 ; C149.2 v1(133.02,28.96) ; v1(76.12,95.12) 76.7,95.7 R22.2 ; v1(67.81,36.32) 67.94,36.2 R26.2 ; v1(82.39,112.81) 82.39,111.46 J17.9 81.07,111.46 v1(81.07,112.81) ; R408.2 R402.2 ; R402.2 R401.2 ; R402.2 v1(106.18,40.01) ; v1(114.73,39.93) 115.07,39.59 R410.2 ; C288.2 v1(148.89,27.43) ; R239.2 154.35,45.85 v1(154.15,46.05) ; R239.2 R238.2 R237.2 R236.2 R235.2 ; R239.2 R240.2 ; v1(119.45,38.1) R412.2 R413.2 ; C289.2 145.97,34.61 v1(145.97,34.67) ; R375.2 92.16,39.43 v1(92.16,40.89) ; v1(65.58,121.41) 65.58,122.94 J17.10 66.59,122.64 v1(66.59,121.28) ; v1(84.96,112.81) 84.96,111.46 J18.8 86.28,111.46 v1(86.28,112.81) ; v1(9.69,57.53) 11.11,57.53 J6.42 10.99,55.54 v1(9.7,55.54) ; D33.1 C183.2 v1(75.87,103.89) ; C287.2 v1(149.91,27.43) ; C125.2 51.79,21.4 v1(52.8,20.4) ; C284.2 v1(146.1,31.37) ; C143.2 v1(131.11,26.67) ; J9.16 v1(167.81,51.15) ; v1(102.08,121.28) 102.08,122.64 J18.11 100.76,122.64 v1(100.76,121.28) ; v1(67.23,103.89) C176.2 C175.2 D31.1 ; C195.2 v1(87.93,103.89) ; C195.2 C196.2 ; C195.2 D35.1 ; v1(71.75,37.15) 72.7,36.2 R25.2 ; v1(94.7,40.26) R376.2 R372.2 ; R321.2 145.51,16.03 v1(145.66,16.18) ; R321.2 v1(144.45,15.24) ; R321.2 143.25,16.03 v1(143.1,16.18) ; v1(99.87,111.74) 101.04,111.74 101.42,111.36 J18.9 101.42,110.24 101.04,109.86 v1(99.87,109.86) ; v2(93.01,100.66) 93.03,100.64 C59.2 ; v1(148.51,13.72) 148.17,13.37 C90.2 ; v1(108.98,31.88) 109.17,31.68 C238.2 ; v2(95.98,102.09) 96.25,101.82 C58.2 ; C199.2 D38.1 v1(92.25,103.89) ; v1(9.82,84.63) 11.11,84.63 J5.42 11.11,86.23 v1(9.82,86.23) ; v1(72.56,103.89) D34.1 C184.2 ; v1(162.35,46.48) 161.57,45.69 161.57,45.01 161.13,44.58 160.34,44.58 159.88,45.03 C85.2 v1(159.05,45.34) ; C150.2 C142.2 133.8,30.99 v1(133.65,30.84) ; v1(71.42,103.89) D32.1 C182.2 ; v1(51.13,37.41) 51.18,37.47 C320.2 R19.2 ; C283.2 v1(147.37,27.43) ; J18.10 84.4,123.3 ; J18.10 85.62,121.82 ; J18.10 86.89,123.3 ; v1(9.82,59.65) 10.73,59.65 J5.41 11.11,61.63 v1(9.82,61.63) ; v1(133.78,26.92) C151.2 C145.2 ; C152.2 v1(127.94,31.37) ; C144.2 v1(128.06,26.54) ; C285.2 v1(148.58,34.49) ; D37.1 C198.2 v1(95.55,103.89) ; v1(91.11,103.89) D36.1 C197.2 ; C86.2 158.77,48.45 Y1.2 159.35,49.99 ; C260.2 v1(157.78,72.26) ; D39.1 v1(20.47,114.45) ; C292.2 v1(152.32,31.88) ; v1(89.07,93.85) 89.07,93.98 89.52,94.43 R66.2 ; C148.2 v1(128.44,30.23) ; C290.2 v1(152.45,33.78) ; C259.2 v1(155.75,73.97) ; J9.19 v1(167.69,52.65) ; v1(81.07,121.28) 81.07,122.64 J17.11 82.39,122.64 v1(82.39,121.28) ; C56.2 97.98,97.87 v2(97.98,98.24) 97.98,98.59 C60.2 ; C291.2 v1(152.32,28.83) ; C261.2 11.8,110.04 v1(11.73,110.11) ; v1(95.68,37.97) 96.16,37.5 R377.2 R378.2 ; R366.2 R367.2 R373.2 v1(83.78,40.01) ; J9.13 v1(167.82,49.65) ; J9.22 167.38,54.15 v1(167.81,53.72) ; C141.2 v1(131.62,32.51) ; v2(94.38,93.8) 94.38,94.33 R50.1 ; C139.2 129.37,26.8 v1(129.97,26.8) ; C140.2 v1(132.98,26.63) ; C208.2 v1(74.45,39.67) ; R374.2 v1(89.37,40.89) ; C293.2 v1(143.43,20.9) ; v1(42.46,45.15) C200.2 ; C240.2 162.38,15.27 v1(163.08,15.27) ; v1(110.33,38.46) 111.18,39.3 R409.2 ; C219.2 85.88,31.68 v1(85.68,31.88) ; v1(47.85,45.15) R343.2 ; C286.2 v1(152.83,27.43) ; C282.2 v1(151.43,33.78) ; v1(67.48,109.86) 66.32,109.86 65.93,110.24 J17.8 65.93,111.36 66.32,111.74 v1(67.48,111.74) ; C227.2 v1(68.44,39.57) ; C262.2 v1(14.4,109.6)
  BOTTOM w0.508: v1(12.87,33.27) 12.87,32.83 J6.41 11.22,32.82 v1(11.22,33.27) ; v1(100.63,17.86) 100.63,17.53 C223.2 101.65,17.48 v1(101.65,17.86) ; J17.5 v1(67.55,106.8)
  vias: v1(8.68,51.44) v1(8.81,26.8) v1(8.81,26.29) v1(8.81,25.78) v1(9.27,51.41) v1(9.32,26.8) v1(9.32,26.29) v1(9.32,25.78) v1(9.44,42.93) v1(9.44,36.7) v1(9.83,45.09) v1(9.83,44.45) v1(9.83,26.8) v1(9.83,26.29) v1(9.83,25.78) v1(10.46,45.09) v1(10.46,44.45) v1(12.09,52.45) v1(12.11,51.92) v1(12.49,41.66) v1(12.62,52.45) v1(12.65,51.92) v1(12.75,29.08) v1(12.75,28.45) v1(12.75,27.18) v1(12.77,30.4) v1(12.77,29.77) v1(13.41,30.4) v1(13.41,29.77) v1(13.38,29.08) v1(13.38,28.45) v1(13.38,27.18) v1(14.88,124.18) v1(15.03,117.35) v1(15.59,112.78) v1(15.79,117.35) v1(15.79,116.71) v1(16.81,7.24) v1(16.81,6.6) v1(16.89,122.68) v1(17.32,99.31) v1(17.32,98.55) v1(17.32,97.79) v1(17.45,7.24) v1(17.45,6.6) v1(17.93,124.18) v1(18.84,114.38) v1(19.48,81.53) v1(19.6,110.87) v1(19.63,52.55) v1(19.63,52.04) v1(19.73,17.27) v1(19.73,16.64) v1(19.73,16) v1(19.73,15.37) v1(20.11,82.8) v1(20.11,82.17) v1(20.11,81.53) v1(20.14,52.55) v1(20.14,52.04) v1(20.24,119.63) v1(20.37,17.27) v1(20.37,16.64) v1(20.37,16) v1(20.37,15.37) v1(20.49,120.9) v1(20.52,109.12) v1(20.62,118.49) v1(20.62,34.54) v1(20.62,33.96) v1(20.62,33.38) v1(20.72,112.78) v1(20.85,124.18) v1(20.87,115.95) v1(21,17.27) v1(21,16.64) v1(21,16) v1(21,15.37) v1(21.26,34.57) v1(21.26,33.99) v1(21.26,33.4) v1(21.64,98.68) v1(21.64,27.81) v1(21.64,27.18) v1(21.64,25.78) v1(21.64,25.15) v1(21.64,17.27) v1(21.64,16.64) v1(21.64,16) v1(21.64,15.37) v1(22.02,121.54) v1(22.02,111) v1(22.27,87.63) v1(22.27,27.81) v1(22.27,27.18) v1(22.27,25.78) v1(22.27,25.15) v1(23.03,88.27) v1(23.03,87.63) v1(23.16,118.36) v1(23.29,115.95) v1(23.29,114.43) v1(23.32,112.78) v1(23.34,109.14) v1(23.54,120.9) v1(23.54,81.53) v1(23.8,119.63) v1(24.28,124.18) v1(24.3,111) v1(24.94,97.92) v1(25.07,85.6) v1(25.68,114.35) v1(26.59,65.66) v1(26.84,89.28) v1(27,122.96) v1(27.56,109.12) v1(28.01,119.61) v1(28.01,116.38) v1(27.96,112.62) v1(28.24,101.85) v1(28.44,65.76) v1(28.44,65.13) v1(28.62,124.16) v1(28.75,71.88) v1(28.75,71.25) v1(28.72,69.65) v1(28.75,69.09) v1(29.05,65.76) v1(29.05,65.13) v1(29.38,80.24) v1(29.38,79.65) v1(29.38,79.07) v1(29.76,29.9) v1(29.76,29.31) v1(29.76,28.63) v1(29.76,28.04) v1(30.02,80.26) v1(30.02,79.68) v1(30.02,79.1) v1(30.17,88.6) v1(30.17,88.01) v1(30.4,29.92) v1(30.4,29.34) v1(30.4,28.65) v1(30.4,28.07) v1(30.7,88.6) v1(30.7,88.01) v1(31.03,122.81) v1(31.16,119.89) v1(31.16,116.71) v1(31.16,54.36) v1(31.39,32.99) v1(31.39,32.41) v1(31.67,124.16) v1(31.67,105.03) v1(31.8,96.01) v1(32.05,54.36) v1(32.05,32.94) v1(32.05,32.36) v1(32.43,88.57) v1(32.43,87.99) v1(32.71,32.94) v1(32.71,32.36) v1(32.76,64.77) v1(32.79,64.16) v1(32.94,92.96) v1(32.94,55.37) v1(32.94,54.74) v1(32.97,88.57) v1(32.97,87.99) v1(33.35,32.94) v1(33.35,32.36) v1(33.57,55.37) v1(33.57,54.74) v1(34.59,124.16) v1(34.57,64.9) v1(34.72,25.78) v1(35,79.35) v1(35,78.77) v1(34.97,55.37) v1(34.97,54.74) v1(35.2,64.92) v1(35.35,25.78) v1(35.53,79.35) v1(35.53,78.77) v1(35.61,122.68) v1(35.61,55.37) v1(35.61,54.74) v1(35.73,117.35) v1(35.71,38.38) v1(35.86,119.76) v1(35.94,25.86) v1(36.55,38.35) v1(36.75,78.61) v1(37.38,78.61) v1(37.54,55.37) v1(37.54,54.61) v1(37.84,47.65) v1(38.02,124.16) v1(38.02,78.61) v1(38.3,63.32) v1(38.3,62.69) v1(38.3,55.37) v1(38.3,54.61) v1(38.48,47.65) v1(39.49,84.18) v1(39.49,83.59) v1(39.57,55.37) v1(39.57,54.61) v1(40.1,84.18) v1(40.1,83.59) v1(40.31,117.35) v1(40.33,55.37) v1(40.33,54.61) v1(40.56,122.81) v1(40.56,120.14) v1(40.71,84.18) v1(40.71,83.59) v1(40.74,36.17) v1(40.74,35.53) v1(40.81,37.97) v1(40.79,37.36) v1(41.07,61.98) v1(41.45,54.36) v1(41.7,61.98) v1(41.8,124.18) v1(42.21,54.36) v1(42.34,61.98) v1(42.29,39.01) v1(42.29,38.38) v1(42.92,39.01) v1(42.92,38.38) v1(43.1,64.03) v1(43.51,23.22) v1(43.51,21.95) v1(43.51,20.68) v1(43.63,123.01) v1(43.63,119.38) v1(43.73,64.03) v1(44.04,116.08) v1(44.47,39.55) v1(44.47,38.91) v1(44.57,113.67) v1(44.78,23.22) v1(44.78,20.68) v1(44.85,124.18) v1(45.11,39.55) v1(45.11,38.91) v1(45.46,83.31) v1(45.46,82.73) v1(45.46,82.14) v1(45.46,81.56) v1(45.51,64.01) v1(45.51,63.37) v1(46.05,23.22) v1(46.05,21.95) v1(46.05,20.68) v1(46.07,83.31) v1(46.07,82.73) v1(46.07,82.14) v1(46.07,81.56) v1(46.15,64.01) v1(46.15,63.37) v1(46.5,37.29) v1(46.5,36.65) v1(46.61,117.32) v1(47.16,121.41) v1(47.16,94.49) v1(47.77,124.18) v1(47.8,94.49) v1(48.05,119.51) v1(48.13,118.26) v1(48.43,94.49) v1(48.59,37.24) v1(48.59,36.6) v1(48.89,14.22) v1(49.07,94.49) v1(49.27,116.43) v1(49.37,118.26) v1(49.65,122.96) v1(49.68,121.23) v1(49.65,119.63) v1(49.7,94.49) v1(49.86,14.22) v1(50.64,118.26) v1(50.85,14.22) v1(51.2,124.18) v1(51.3,122.96) v1(51.33,121.23) v1(51.3,119.63) v1(51.86,118.11) v1(51.86,14.22) v1(51.99,15.11) v1(52.68,15.01) v1(52.75,117.73) v1(52.75,14.22) v1(52.75,13.21) v1(52.9,122.96) v1(52.93,121.23) v1(52.9,119.63) v1(53.26,116.84) v1(54.07,116.87) v1(54.38,124.16) v1(54.58,122.96) v1(54.61,121.23) v1(54.58,119.63) v1(54.66,118.34) v1(54.78,38.73) v1(55.04,36.7) v1(55.09,116.87) v1(55.16,23.5) v1(55.8,23.5) v1(55.98,116.87) v1(56.36,123.04) v1(56.38,121.31) v1(56.36,119.71) v1(56.43,118.31) v1(56.69,36.58) v1(56.96,116.89) v1(57.32,36.58) v1(57.43,124.16) v1(57.76,116.87) v1(57.96,36.58) v1(58.09,72.14) v1(58.29,123.06) v1(58.31,121.34) v1(58.29,119.74) v1(58.34,23.37) v1(58.59,36.58) v1(58.72,118.11) v1(58.72,40.64) v1(58.72,40.01) v1(58.72,38.48) v1(58.72,37.85) v1(58.85,48.13) v1(59.36,40.64) v1(59.36,40.01) v1(59.36,38.48) v1(59.36,37.85) v1(59.48,23.37) v1(59.74,25.27) v1(59.86,69.34) v1(59.86,66.29) v1(59.99,123.09) v1(60.02,121.36) v1(59.99,119.76) v1(60.24,115.82) v1(60.35,124.16) v1(60.27,118.26) v1(60.63,94.61) v1(61.18,121.44) v1(61.31,119.81) v1(61.26,94.61) v1(61.44,118.26) v1(61.49,52.07) v1(61.64,25.65) v1(62.18,88.19) v1(62.18,87.68) v1(62.28,25.65) v1(62.43,119.66) v1(62.4,118.36) v1(62.4,115.95) v1(62.66,94.61) v1(62.68,88.19) v1(62.68,87.68) v1(62.91,26.92) v1(63.14,88.62) v1(63.22,89.31) v1(63.29,94.61) v1(63.38,121.41) v1(63.55,116.71) v1(63.72,89.31) v1(63.7,88.65) v1(63.67,26.92) v1(63.78,124.16) v1(63.8,13.21) v1(63.8,12.45) v1(63.8,11.68) v1(64.27,119.51) v1(64.31,117.86) v1(64.44,26.92) v1(64.44,11.68) v1(65.07,26.92) v1(65.2,23.37) v1(65.2,22.48) v1(65.2,21.84) v1(65.32,120.02) v1(65.27,112.81) v1(65.83,21.84) v1(66.59,112.81) v1(68.96,124.16) v1(69.9,118.36) v1(70.09,20.7) v1(70.09,19.68) v1(70.09,18.67) v1(70.66,120.14) v1(70.89,95.2) v1(71.04,122.94) v1(71.11,20.7) v1(71.11,19.68) v1(71.11,18.67) v1(71.17,110.62) v1(71.29,120.14) v1(71.42,95.2) v1(71.8,110.62) v1(71.93,120.14) v1(72.01,124.16) v1(72.12,20.7) v1(72.12,19.68) v1(72.12,18.67) v1(72.44,110.62) v1(72.44,14.1) v1(72.44,13.46) v1(72.51,95.17) v1(72.94,14.1) v1(72.94,13.46) v1(73.05,95.17) v1(73.71,122.94) v1(74.21,118.49) v1(74.72,95.12) v1(74.93,124.16) v1(75.48,95.12) v1(77.39,17.91) v1(77.39,17.27) v1(78.2,8.74) v1(78.36,124.16) v1(78.79,13.34) v1(78.79,12.57) v1(78.79,11.81) v1(78.84,8.74) v1(79.42,118.36) v1(79.42,11.81) v1(79.55,96.27) v1(79.55,8.76) v1(79.55,8.13) v1(79.55,7.49) v1(80.03,107.59) v1(80.18,8.76) v1(80.18,8.13) v1(80.18,7.49) v1(80.59,107.58) v1(80.72,34.14) v1(81.28,34.14) v1(83.18,96.8) v1(83.18,96.16) v1(83.74,118.36) v1(83.82,96.8) v1(83.82,96.16) v1(83.97,124.18) v1(85.56,37.85) v1(85.75,96.85) v1(85.75,96.22) v1(86.13,37.85) v1(86.41,120.27) v1(86.38,96.85) v1(86.38,96.22) v1(86.76,110.34) v1(86.91,106.81) v1(87.02,124.18) v1(87.04,120.27) v1(87.4,110.34) v1(87.55,106.81) v1(87.68,120.27) v1(88.03,110.34) v1(88.58,33.65) v1(88.58,32.38) v1(88.58,31.11) v1(89.33,118.36) v1(89.85,33.65) v1(89.85,32.38) v1(89.85,31.11) v1(89.94,124.18) v1(90.98,120.52) v1(91.12,33.65) v1(91.12,32.38) v1(91.12,31.11) v1(91.23,122.68) v1(93.37,124.18) v1(95.04,122.81) v1(95.17,120.4) v1(96.14,124.18) v1(98.09,25.53) v1(98.47,122.81) v1(98.85,27.18) v1(98.98,20.19) v1(99.18,124.18) v1(99.36,120.52) v1(99.87,16.89) v1(100.63,18.67) v1(101.65,25.4) v1(101.65,18.67) v1(101.9,27.18) v1(102.54,17.02) v1(103.12,124.21) v1(103.3,20.19) v1(104.06,98.42) v1(104.11,40.61) v1(104.11,40.08) v1(104.69,98.42) v1(107.87,98.3) v1(108.5,98.3) v1(108.85,37.85) v1(111.93,97.28) v1(111.93,96.65) v1(111.87,33.65) v1(111.87,32.38) v1(111.87,31.11) v1(112.57,97.28) v1(112.57,96.65) v1(113.14,33.65) v1(113.14,32.38) v1(113.14,31.11) v1(114.41,33.65) v1(114.41,32.38) v1(114.41,31.11) v1(114.6,66.93) v1(114.6,66.42) v1(114.6,65.91) v1(115.24,94.11) v1(115.24,93.47) v1(115.87,94.11) v1(115.87,93.47) v1(116.89,91.69) v1(120.06,67.82) v1(120.82,67.82) v1(121.08,20.07) v1(121.08,19.38) v1(121.08,18.59) v1(121.43,24.77) v1(121.41,24.16) v1(121.71,19.38) v1(121.71,18.59) v1(122.04,24.18) v1(122.73,94.23) v1(122.73,93.6) v1(123.36,94.23) v1(123.36,93.6) v1(123.95,58.04) v1(124,94.23) v1(124,93.6) v1(124.51,58.06) v1(125.14,58.7) v1(125.14,58.06) v1(126.67,71.63) v1(126.79,67.82) v1(126.79,65.28) v1(126.79,64.01) v1(127.05,22.1) v1(127.3,71.63) v1(127.55,67.82) v1(127.55,65.28) v1(127.55,64.01) v1(127.68,22.1) v1(129.08,94.11) v1(129.08,93.47) v1(129.46,91.95) v1(129.46,91.31) v1(129.71,94.11) v1(129.71,93.47) v1(135.17,81.03) v1(135.43,94.23) v1(135.43,93.6) v1(136.06,94.23) v1(136.06,93.6) v1(136.06,79.3) v1(136.44,91.69) v1(136.7,94.23) v1(136.7,93.6) v1(136.95,80.77) v1(139.49,94.49) v1(139.49,91.69) v1(139.49,91.06) v1(140.13,91.69) v1(140.13,91.06) v1(140.76,82.42) v1(142.29,82.55) v1(142.79,93.85) v1(143.13,15.24) v1(143.79,15.24) v1(144.19,54.74) v1(144.7,54.74) v1(144.95,79.38) v1(145.06,15.24) v1(145.21,93.85) v1(145.21,54.74) v1(145.72,15.27) v1(146.22,82.42) v1(147.11,32.64) v1(147.11,31.62) v1(147.11,30.61) v1(147.11,29.59) v1(147.11,28.57) v1(147.62,94.23) v1(148.13,80.14) v1(148.13,32.64) v1(148.13,31.62) v1(148.13,30.61) v1(148.13,29.59) v1(148.13,28.57) v1(148.64,63.63) v1(148.76,93.98) v1(148.76,93.22) v1(149.14,32.64) v1(149.14,31.62) v1(149.14,30.61) v1(149.14,29.59) v1(149.14,28.57) v1(149.27,91.82) v1(149.27,52.76) v1(149.65,95.5) v1(149.65,94.74) v1(149.65,93.98) v1(149.65,93.22) v1(150.03,63.63) v1(150.16,32.64) v1(150.16,31.62) v1(150.16,30.61) v1(150.16,29.59) v1(150.16,28.57) v1(150.67,51.69) v1(150.92,91.82) v1(150.92,91.19) v1(151.18,32.64) v1(151.18,31.62) v1(151.18,30.61) v1(151.18,29.59) v1(151.18,28.57) v1(151.3,82.42) v1(151.56,91.82) v1(151.56,91.19) v1(151.68,63.63) v1(152.57,80.01) v1(153.97,52.86) v1(154.35,54.86) v1(154.35,54.36) v1(154.86,54.86) v1(154.86,54.36) v1(157.78,29.34) v1(160.93,96.52) v1(160.93,96.01) v1(160.96,95.5) v1(161.21,42.16) v1(161.21,41.53) v1(161.44,96.55) v1(161.46,96.01) v1(161.46,95.5) v1(161.72,29.34) v1(161.84,87.12) v1(161.84,86.23) v1(161.84,42.16) v1(161.84,41.53) v1(162.23,97.92) v1(162.35,92.33) v1(162.48,87.12) v1(162.48,86.23) v1(162.86,97.92) v1(162.86,36.58) v1(162.99,25.53) v1(163.11,69.09) v1(163.11,66.93) v1(163.52,11.65) v1(163.62,97.92) v1(164.26,97.92) v1(164.49,11.65) v1(164.87,97.92) v1(165.81,11.8) v1(166.77,11.8) v1(166.92,39.75) v1(167.43,65.79) v1(167.43,65.15) v1(167.56,91.69) v1(167.56,39.75) v1(167.69,58.8) v1(168.07,65.79) v1(168.07,65.15) v1(168.07,55.63) v1(168.07,54.99) v1(168.19,45.34) v1(168.19,44.7) v1(168.19,39.75) v1(168.58,74.55) v1(168.7,65.79) v1(168.7,65.15) v1(168.7,55.63) v1(168.7,54.99) v1(168.83,58.8) v1(168.83,45.34) v1(168.83,44.7) v1(168.83,39.75) v1(168.86,83.69) v1(168.86,83.06) v1(168.86,82.42) v1(169.21,80.26) v1(169.21,79.63) v1(169.41,83.06) v1(170.23,76.61) v1(170.73,32.26) v1(170.86,76.61) v1(170.86,20.83) v1(170.86,17.27) v1(170.99,28.57) v1(170.99,25.15) v1(171.12,97.28) v1(171.12,96.77) v1(171.37,91.69) v1(171.37,74.17) v1(171.5,76.61) v1(171.62,97.28) v1(171.62,96.77) v1(171.88,37.21) v1(172.13,92.71) v1(172.26,32.26) v1(172.26,28.7) v1(172.26,20.95) v1(172.39,64.01) v1(172.39,25.15) v2(21.14,49.24) v2(21.8,49.24) v2(21.92,73.55) v2(22.15,47.43) v2(22.82,47.43) v2(23.17,45.66) v2(23.33,75.69) v2(23.54,74.04) v2(23.83,45.66) v2(24.2,43.89) v2(24.65,42.44) v2(24.94,75.18) v2(24.86,43.9) v2(25.26,77.59) v2(25.92,77.59) v2(25.99,79.17) v2(26.43,42.44) v2(27.44,43.81) v2(27.7,81.5) v2(28.36,81.5) v2(29.22,43.81) v2(33.91,35.74) v2(33.91,35.13) v2(34.51,35.74) v2(34.51,35.13) v2(38.22,81.46) v2(38.22,80.85) v2(38.83,81.46) v2(38.83,80.85) v2(49.22,42.95) v2(49.49,51.56) v2(50.44,42.93) v2(51.26,53.59) v2(51.26,51.56) v2(53.04,53.59) v2(53.17,54.86) v2(54.82,56.52) v2(54.95,54.86) v2(54.87,53.34) v2(54.86,3.5) v2(55.29,9.27) v2(55.46,15.11) v2(56.6,56.52) v2(56.6,15.11) v2(56.64,3.5) v2(56.65,53.34) v2(56.69,9.27) v2(60.41,65.59) v2(60.46,62.56) v2(60.46,59.67) v2(60.46,56.56) v2(60.46,54.83) v2(62.19,65.59) v2(62.24,62.56) v2(62.24,59.67) v2(62.24,56.56) v2(62.24,54.83) v2(66.39,40.26) v2(68.17,40.26) v2(69.96,3.62) v2(71.74,3.62) v2(72.39,42.67) v2(74.17,42.67) v2(75.39,42.67) v2(76.85,41.02) v2(77.17,42.67) v2(78.39,41.91) v2(78.62,41.02) v2(80.17,41.91) v2(81.39,41.53) v2(83.08,41.83) v2(126.28,24.59) v2(138.98,30.61) v2(155.32,51.42) v2(155.97,54.4) v2(155.95,52.84) v2(156.09,57.38) v2(156.09,56.06) v2(157.1,51.42) v2(157.74,54.4) v2(157.73,52.84) v2(157.87,57.38) v2(157.87,56.06)
GND_EARTH: length 15.8
  TOP w0.381: v1(51.99,9.27) 51.99,10.13 R320.2 50.97,10.13 v1(50.97,9.27) ; v1(143.1,13.28) C170.2 144.45,13.26 v1(144.45,12.34) ; v1(48.81,9.27) 48.81,9.98 C165.2 49.7,10.11 v1(49.7,9.27) ; v1(100.63,13.08) 100.63,13.79 R574.1 101.65,13.79 v1(101.65,13.08)
  BOTTOM w0.508: v1(100.63,13.08) 100.63,13.56 C223.1 101.65,13.61 v1(101.65,13.08)
  BOTTOM w1.016: MTG3.1 MTG3.9
  vias: v1(5.89,119.38) v1(5.89,116.46) v1(5.89,113.41) v1(5.89,109.98) v1(5.89,106.93) v1(5.89,103.5) v1(5.89,100.46) v1(5.89,97.54) v1(5.89,94.11) v1(5.89,91.06) v1(5.89,87.63) v1(5.89,84.58) v1(5.89,81.15) v1(5.89,78.11) v1(5.89,74.68) v1(5.89,71.63) v1(5.89,68.71) v1(5.89,65.28) v1(5.89,62.23) v1(5.89,59.94) v1(5.89,56.9) v1(5.89,53.47) v1(5.89,50.42) v1(5.89,46.99) v1(5.89,43.94) v1(5.89,41.02) v1(5.89,37.59) v1(5.89,34.54) v1(5.89,31.88) v1(5.89,28.83) v1(5.89,25.4) v1(5.89,22.35) v1(5.89,18.92) v1(5.89,15.88) v1(5.89,12.95) v1(5.89,9.53) v1(5.89,6.48) v1(7.03,117.6) v1(9.44,116.84) v1(9.44,115.95) v1(10.21,116.84) v1(10.21,115.95) v1(12.11,124.08) v1(12.11,122.05) v1(12.11,119.25) v1(12.24,0.89) v1(15.16,2.79) v1(15.16,2.16) v1(15.67,0.89) v1(15.79,2.79) v1(15.79,2.16) v1(18.21,0.89) v1(20.62,0.89) v1(23.16,0.89) v1(28.11,0.89) v1(30.65,0.89) v1(33.96,0.89) v1(37.38,0.89) v1(39.92,0.89) v1(42.97,0.89) v1(46.4,0.89) v1(48.81,8.56) v1(49.45,0.89) v1(49.7,8.56) v1(50.97,8.56) v1(51.99,8.56) v1(53.51,0.89) v1(55.8,0.89) v1(58.59,0.89) v1(62.02,0.76) v1(62.35,6.58) v1(62.35,5.11) v1(62.43,3.53) v1(64.21,0.79) v1(64.54,6.6) v1(64.54,5.13) v1(64.61,3.56) v1(69.26,0.89) v1(72.31,0.89) v1(76.75,4.95) v1(77.01,0.89) v1(77.09,3.94) v1(77.09,3.3) v1(77.77,3.94) v1(77.77,3.3) v1(78.41,3.94) v1(78.41,3.3) v1(79.09,3.94) v1(79.09,3.3) v1(79.55,4.95) v1(80.06,0.89) v1(83.49,0.89) v1(86.03,0.89) v1(89.07,0.89) v1(92.5,0.89) v1(95.55,0.89) v1(99.11,0.89) v1(99.87,14.1) v1(100.63,12.32) v1(101.65,12.32) v1(102.15,0.89) v1(102.41,14.22) v1(105.58,0.89) v1(108.63,0.89) v1(112.06,0.89) v1(115.24,0.89) v1(118.28,0.89) v1(121.59,16) v1(121.71,0.89) v1(122.37,14.99) v1(122.37,14.22) v1(123.52,14.99) v1(123.52,14.22) v1(124.25,16) v1(124.76,0.89) v1(128.32,0.89) v1(131.36,0.89) v1(134.79,0.89) v1(137.84,0.89) v1(141.27,0.89) v1(143.1,12.34) v1(143.07,11.63) v1(143.43,0.89) v1(143.76,12.32) v1(143.84,11.61) v1(145.11,12.32) v1(146.48,0.89) v1(149.91,0.89) v1(152.95,0.89) v1(156.51,0.89) v1(159.56,0.89) v1(162.99,0.89) v1(163.11,3.56) v1(163.32,5.94) v1(163.32,5.16) v1(164.33,5.97) v1(164.33,5.18) v1(165.63,5.21) v1(165.65,5.99) v1(165.91,3.56) v1(166.04,0.89) v1(166.65,5.21) v1(166.67,5.99) v1(169.46,0.89) v1(174.16,118.87) v1(174.16,115.82) v1(174.16,112.39) v1(174.16,109.35) v1(174.16,105.92) v1(174.16,102.87) v1(174.16,100.08) v1(174.16,97.03) v1(174.16,93.6) v1(174.16,90.55) v1(174.16,87.12) v1(174.16,84.07) v1(174.16,80.9) v1(174.16,77.85) v1(174.16,74.42) v1(174.16,71.37) v1(174.16,67.94) v1(174.16,64.9) v1(174.16,61.59) v1(174.16,58.55) v1(174.16,55.12) v1(174.16,52.07) v1(174.16,48.64) v1(174.16,45.59) v1(174.16,42.04) v1(174.16,38.99) v1(174.16,35.56) v1(174.16,32.51) v1(174.16,29.08) v1(174.16,26.04) v1(174.16,23.11) v1(174.16,19.68) v1(174.16,16.64) v1(174.16,14.48) v1(174.16,12.19) v1(174.16,10.92) v1(174.16,9.65) v1(174.16,8.51) v1(174.16,5.84)
VDD_1V2:
  vias: v2(151.81,56.13) v2(151.81,55.63) v2(151.81,20.83) v2(151.76,20.32) v2(152.32,56.13) v2(152.32,55.63) v2(152.27,20.32) v2(152.73,20.32) v2(155.39,49.25) v2(155.39,48.74) v2(155.9,49.25) v2(155.9,48.74) v2(160.78,38.35) v2(160.78,37.85) v2(161.29,38.35) v2(161.29,37.85)
VDD_1V8: length 222.1
  TOP w0.203: v1(153.46,69.6) 153.84,69.22 U18.3 ; v1(156.76,73.53) 157.01,73.28 U45.6 ; v1(155.75,73.09) 155.56,73.28 U45.3 ; U18.6 v1(156.9,69.22)
  TOP w0.254: 43.99,25.4 44,25.39 U27.30
  TOP w0.305: U55.B4 v2(96.98,102.09) ; R23.1 C36.1 v1(81.96,94.74) ; v1(78.99,95.25) 78.91,95.33 78.91,95.39 78.61,95.7 U4.5 ; R49.1 94.28,94.41 v2(93.72,93.85) ; U55.E4 v2(96.98,98.24) ; U55.D1 v2(93.01,99.66)
  TOP w0.381: R68.1 v1(90.41,112.71) ; R157.1 v1(151.05,72.77) ; U8.5 v1(91.87,111.45) 91.36,111.45 C57.1 ; R64.1 100.78,93.69 v1(100.78,93.19) ; R154.1 v1(151.18,68.71) ; R153.1 v1(160.96,68.71) ; 43.99,25.4 C137.1 v1(43.26,26.99) ; R156.1 v1(161.08,72.77) ; C87.1 v1(153.46,69.6)
  ART03 w0.305: v1(81.96,94.74) 79.5,94.74 v1(78.99,95.25)
  ART03 w0.381: v1(157.33,49.09) 160.47,45.95 v1(160.57,45.95) 160.57,45.21 162.05,43.74 164.16,43.74 164.74,43.15 168.3,43.15 169.41,44.27 169.41,66.19 162.84,72.77 v1(161.08,72.77)
  ART03 w0.508: v1(11.6,103.2) 11.91,103.5 18.13,103.5 19.1,102.54 19.1,89.94 12.29,83.13 12.29,63.42 15.29,60.43 15.29,36.58 v1(17.71,34.15)
  BOTTOM w0.381: v2(93.72,93.85) 93.39,94.18 R47.1 R42.1 R48.1 R65.1 ; C56.1 96.98,97.75 v2(96.98,98.24) 96.98,98.72 C60.1 ; v1(96.24,93.6) 96.06,93.78 R46.1 R41.1 R44.1 R45.1 R43.1 ; v1(81.96,94.74) 82.42,95.2 82.42,97.36 84.68,99.62 v1(84.68,100.71) ; v1(90.41,112.71) 90.41,112.25 91.22,111.45 v1(91.87,111.45) 91.88,111.45 92.58,110.74 94.76,110.74 95.98,109.52 95.98,106.32 96.72,105.59 96.72,102.35 v2(96.98,102.09) 97.13,101.94 C58.1 ; C85.1 160.57,45.52 v1(160.57,45.95) 161.15,46.53 Y1.4 ; R149.1 v1(157.33,49.09) ; v2(93.01,99.66) 93.67,99.66 C59.1 ; C259.1 v1(155.75,73.09)
  BOTTOM w0.508: v1(43.26,26.99) 43.26,28.67 41.98,29.95 37.94,29.95 35.91,27.91 33.42,27.91 26.08,35.26 18.82,35.26 v1(17.71,34.15)
  vias: v1(11.63,102.54) v1(84.68,101.32) v1(85.29,101.32) v1(85.29,100.74) v1(85.9,101.32) v1(85.9,100.74) v1(115.24,97.43) v1(115.79,97.41) v1(116.35,97.41) v1(116.89,97.41) v1(117.39,97.41) v1(117.9,97.41)
VDD_1V8_FB: length 3.9
  TOP w0.305: U4.7 79.76,97 80.23,96.52 R24.1 R23.2 C36.2
VDD_3V3: length 209.6
  TOP w0.203: v1(158.67,69.6) 158.55,69.72 U18.7 ; U46.6 16.43,109.35 v1(16.68,109.6) 16.43,109.85 U46.7 ; U45.7 v1(158.67,73.78) ; U46.3 11.74,109.35 v1(11.73,109.35) ; U29.12 57.23,18.2 v1(56.69,17.65) C153.1 ; 146.5,70.89 U42.24
  TOP w0.254: v1(136.51,30.29) 136.46,30.34 U28.32 ; v1(131.62,34.8) 131.61,34.79 U28.41 ; v1(65.2,30.35) 65.2,30.36 U54.16 ; U28.27 136.04,27.84 v1(136.19,27.69) ; U28.19 131.11,24.26 v1(131.11,24.26) ; U27.20 48.63,21.72 v1(48.71,21.64) ; U28.13 v1(128.11,24.3)
  TOP w0.305: C71.1 158.16,81.92 v1(158.15,81.93) U13.5 ; U3.5 53.84,38.17 54.15,37.86 v1(54.15,37.34) ; v1(159.12,85.22) C70.1 159.01,85.74 U12.5
  TOP w0.381: v1(149.53,68.45) 149.53,67.94 149.14,67.56 R438.1 ; R498.1 v1(135.37,70.16) ; Q7.1 v1(75.18,22.48) ; 146.5,70.89 146.73,71.12 C253.1 v1(147.69,71.7) ; C88.1 v1(158.67,69.6) ; R278.1 v1(117.71,90.81) ; C319.1 v1(65.2,30.35) ; R563.1 v1(78.66,27.1) ; v1(72.03,26.31) 72.32,26.6 R558.1 ; R417.1 v1(161.28,30.99) ; R426.1 v1(98.98,116.08) ; R308.1 R310.1 v1(62.02,19.68) ; R539.1 v1(129.65,67.29) ; R559.1 67.63,25.38 68.28,24.73 v1(68.28,24.3) Q6.1 ; R379.1 v1(119.26,25.5) ; R147.1 v1(16.68,96.14) ; R159.1 v1(151.18,70.48) ; R266.1 v1(130.41,90.93) ; R316.1 v1(54.78,30.61) ; R344.1 v1(97.11,25.15) ; R380.1 v1(104.28,25.4) ; R395.1 107.96,39.51 107.49,39.98 v1(107.06,39.98) ; R345.1 v1(81.62,25.27) ; v1(81.2,27.43) 81.44,27.43 FB8.1 81.44,26.67 v1(81.2,26.67) ; R158.1 v1(160.96,70.48) ; R301.1 v1(132,37.59) ; R311.1 R309.1 v1(54.4,19.56) ; R300.1 v1(128.06,37.59) ; v1(138.03,34.23) R304.1 R305.1 R306.1 ; v1(23.8,42.39) 23.8,41.81 v1(21.84,39.85) 19.1,37.11 v1(18.16,37.11) ; Y2.4 v1(50.58,20.57) 50.92,20.24 R289.1 ; R423.1 v1(93.39,116.08) ; R360.1 v1(84.67,40.01) ; R427.1 v1(96.31,116.08) ; Q8.1 v1(75.15,26.24) ; Q1.1 v1(71.8,23.65) ; R94.1 v1(162.61,79.88) ; v1(81,35.03) 80.77,34.8 R557.1 ; R521.1 v1(144.06,52.7) ; U35.5 v1(76.07,39.05) ; R424.1 v1(101.65,116.08) ; R561.1 78.69,20.47 77.9,19.68 v1(77.14,19.68) R248.1 ; R312.1 v1(62.02,17.91) ; R103.1 v1(152.64,86.36) ; R303.2 v1(133.78,37.59) ; v1(57.32,37.72) C37.1 R18.1
  TOP w0.508: v1(69.32,39.57) 69.32,39.2 U39.5 ; v1(80.84,102.77) 85.49,102.77 85.82,103.1 88.77,103.1 94.08,108.41 96.49,108.41 98.98,110.9 v1(98.98,116.08)
  ART03 w0.381: v1(57.32,37.72) 57.32,40.51 59.61,42.8 v1(62.02,42.8) ; v1(150.16,20.32) 150.16,18.62 151.81,16.97 156.76,16.97 159.51,14.22 v1(163.04,14.22)
  BOTTOM w0.381: R456.1 R460.1 148.57,68.83 148.95,68.45 v1(149.53,68.45) ; R544.1 76.25,97.66 v1(75.61,98.3) ; v1(16.68,96.14) 10.38,102.44 10.38,104.47 11.27,105.36 11.27,108.89 v1(11.73,109.35) 12.43,109.35 C261.1 12.63,109.16 13.31,108.48 15.54,108.48 15.85,108.8 C262.1 v1(16.68,109.6) ; R143.1 v1(18.16,37.11) ; C125.1 50.58,21.26 v1(50.58,20.57) ; C142.1 135.56,30.99 136.25,30.29 v1(136.51,30.29) ; 24.84,67.06 20.87,67.06 19.88,66.07 19.13,66.07 R467.1 ; 24.84,67.06 24.84,67.72 v1(25.85,68.73) ; 24.84,67.06 24.84,66.14 24.46,65.76 22.55,65.76 21.05,64.26 R145.1 ; v1(161.27,73.79) 161.01,73.79 R428.1 ; R431.1 R432.1 156.03,39.4 v1(156.03,39.95) ; v1(23.8,42.39) 22.53,42.39 R135.1 R133.1 ; R429.1 151.88,73.97 152.19,73.66 v1(152.9,73.66) ; C260.1 158.48,73.97 v1(158.67,73.78) ; R414.1 v1(163.04,14.22) ; R471.1 v1(129.65,69.34) ; C139.1 128.16,25.18 C144.1 128.06,24.35 v1(128.11,24.3) ; v1(45.64,28.96) 45.77,28.83 R435.1 R434.1 ; v1(76.07,39.05) 75.42,39.05 75.36,38.99 C208.1 ; R363.1 v1(73.96,37.21) ; v1(58.96,25.64) 59.3,25.98 R318.1 ; R468.1 v1(18.9,69.09) ; R398.1 v1(67.86,37.18) ; R136.1 R134.1 v1(21.41,70.26) ; C145.1 136.06,27.81 v1(136.19,27.69) ; C141.1 v1(131.62,34.8) ; R416.1 v1(162.86,21.97) ; v1(57.07,21.9) R473.1 R474.1 ; R396.1 v1(67.54,39.57) ; R361.1 v1(73.55,39.62) ; R160.1 v1(160.32,43.31) ; R470.1 v1(115.18,71.19) ; C227.1 v1(69.32,39.57) ; v1(21.84,39.85) 20.8,39.85 20.49,40.16 R437.1 ; v1(131.11,24.26) C143.1 131.21,25.18 C140.1
  vias: v1(33.83,29.06) v1(34.39,29.06) v1(34.92,29.06) v1(35.45,29.08) v1(44.4,31.85) v1(44.42,31.34) v1(44.93,31.85) v1(44.95,31.34) v1(62.02,44.07) v1(62.02,43.43) v1(62.66,44.07) v1(62.66,43.43) v1(62.66,42.8) v1(64.44,94.49) v1(64.44,93.98) v1(65.07,94.49) v1(65.07,93.98) v1(80.82,103.38) v1(81,35.59) v1(101.61,40.13) v1(102.37,40.13) v1(103.13,40.13) v1(113.97,91.82) v1(113.97,91.19) v1(114.6,91.82) v1(114.6,91.19) v1(122.35,57.91) v1(122.35,57.28) v1(122.98,57.91) v1(122.98,57.28) v1(126.41,92.46) v1(126.41,91.69) v1(127.05,92.46) v1(127.05,91.69) v1(139.49,93.22) v1(139.49,92.58) v1(140.13,93.22) v1(140.13,92.58) v1(145.84,56.39) v1(146.48,56.39) v1(149.53,20.32) v1(150.92,93.34) v1(150.92,92.71) v1(151.56,93.34) v1(151.56,92.71) v1(162.66,38.35) v1(162.66,37.85) v1(163.17,38.35) v1(163.17,37.85) v1(163.62,85.47) v1(163.62,84.84) v1(164.26,85.47) v1(164.26,84.84) v1(170.79,40.26) v1(170.79,39.75) v1(171.29,40.26) v1(171.32,39.75)
